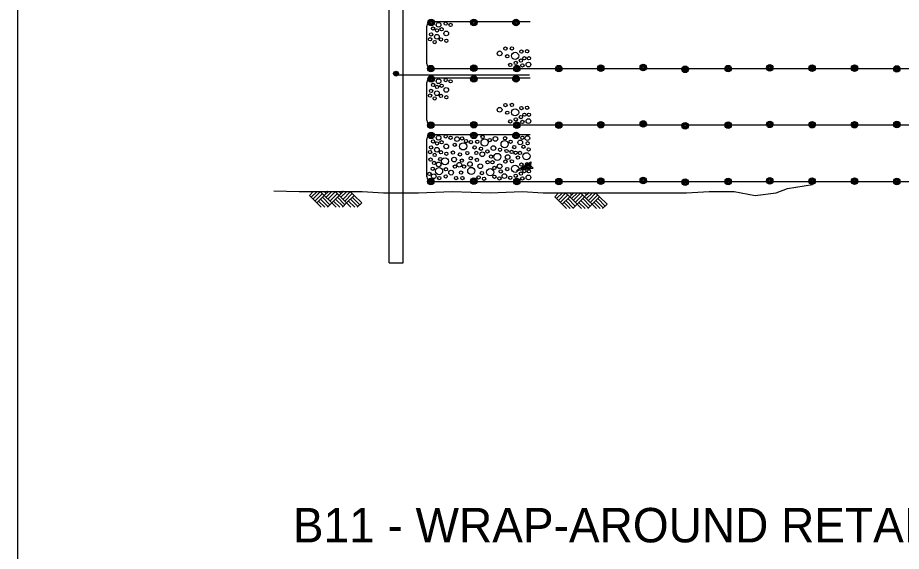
# Model space of a CAD drawing. Extents: x -0.04 to 2.79, y -0.02 to 1.81.
# Drawn here: x 2.1162 to 2.3837, y 0.9292 to 1.0907 of the extents above; entities that cross this region are included whole.
import ezdxf

# ---------------------------------------------------------------- set-up
doc = ezdxf.new("R2010")
doc.units = 0
doc.layers.add('Level 1', color=7, linetype='Continuous')

msp = doc.modelspace()

# ---------------------------------------------------------------- linework, layer by layer
msp.add_line((2.11617, 1.73185), (2.11617, 0.08028))
at = {"layer": 'Level 1'}
for p, q in [((2.22861, 1.03829), (2.22861, 1.23015)), ((2.23285, 1.03829), (2.23285, 1.23015)), ((2.2414, 1.08955), (2.27133, 1.08955)), ((2.24003, 1.07677), (2.24003, 1.08818)), ((2.23066, 1.07342), (2.27113, 1.07342)), ((2.24003, 1.07533), (2.24003, 1.07533)), ((2.2414, 1.07533), (2.39949, 1.07533)), ((2.24003, 1.05968), (2.24003, 1.07109)), ((2.2414, 1.07246), (2.27133, 1.07246)), ((2.24003, 1.05824), (2.24003, 1.05824)), ((2.2414, 1.05824), (2.4012, 1.05824)), ((2.2414, 1.05537), (2.27133, 1.05537)), ((2.24003, 1.04259), (2.24003, 1.05401)), ((2.26723, 1.04444), (2.27154, 1.0471)), ((2.26846, 1.04485), (2.2712, 1.04656)), ((2.26962, 1.04526), (2.27092, 1.04608)), ((2.27092, 1.04608), (2.27092, 1.04574)), ((2.2712, 1.04656), (2.27113, 1.0458)), ((2.27154, 1.0471), (2.2714, 1.04594)), ((2.26723, 1.04444), (2.27222, 1.04512)), ((2.26846, 1.04485), (2.27167, 1.04526)), ((2.26962, 1.04526), (2.27113, 1.04546)), ((2.27092, 1.04574), (2.27113, 1.04546)), ((2.27113, 1.0458), (2.27167, 1.04526)), ((2.2714, 1.04594), (2.27222, 1.04512)), ((2.24003, 1.04116), (2.24003, 1.04116)), ((2.2414, 1.04116), (2.40462, 1.04116)), ((2.20449, 1.03692), (2.20565, 1.03815)), ((2.20503, 1.03637), (2.20681, 1.03815)), ((2.20558, 1.03582), (2.20784, 1.03808)), ((2.209, 1.03692), (2.20777, 1.03815)), ((2.20954, 1.03753), (2.20893, 1.03815)), ((2.209, 1.03692), (2.21023, 1.03815)), ((2.209, 1.03692), (2.21023, 1.03815)), ((2.20954, 1.03637), (2.21132, 1.03815)), ((2.21009, 1.03808), (2.21002, 1.03815)), ((2.21009, 1.03582), (2.21241, 1.03808)), ((2.21351, 1.03692), (2.21228, 1.03815)), ((2.21405, 1.03753), (2.21344, 1.03815)), ((2.21351, 1.03692), (2.21474, 1.03815)), ((2.21351, 1.03692), (2.21474, 1.03815)), ((2.21405, 1.03637), (2.21583, 1.03815)), ((2.21467, 1.03808), (2.21453, 1.03815)), ((2.21467, 1.03582), (2.21693, 1.03808)), ((2.21802, 1.03692), (2.21686, 1.03815)), ((2.22861, 1.01648), (2.22861, 1.03829)), ((2.23285, 1.01648), (2.23285, 1.03829)), ((2.20674, 1.03466), (2.20449, 1.03692)), ((2.20613, 1.03521), (2.20845, 1.03753)), ((2.20674, 1.03466), (2.209, 1.03692)), ((2.21009, 1.03357), (2.20784, 1.03582)), ((2.21071, 1.03412), (2.20845, 1.03637)), ((2.21125, 1.03466), (2.209, 1.03692)), ((2.21071, 1.03521), (2.21296, 1.03753)), ((2.21125, 1.03466), (2.21351, 1.03692)), ((2.21467, 1.03357), (2.21241, 1.03582)), ((2.21522, 1.03412), (2.21296, 1.03637)), ((2.21706, 1.03336), (2.21351, 1.03692)), ((2.21522, 1.03521), (2.21747, 1.03753)), ((2.21576, 1.03466), (2.21802, 1.03692)), ((2.21918, 1.03357), (2.21693, 1.03582)), ((2.21973, 1.03412), (2.21747, 1.03637)), ((2.22034, 1.03466), (2.21802, 1.03692)), ((2.27878, 1.03651), (2.27995, 1.03774)), ((2.28104, 1.03425), (2.27878, 1.03651)), ((2.27933, 1.03596), (2.28111, 1.03774)), ((2.27988, 1.03535), (2.28213, 1.03767)), ((2.28042, 1.0348), (2.28275, 1.03706)), ((2.28104, 1.03425), (2.28329, 1.03651)), ((2.28329, 1.03651), (2.28206, 1.03774)), ((2.28439, 1.03309), (2.28213, 1.03535)), ((2.285, 1.03371), (2.28275, 1.03596)), ((2.28384, 1.03706), (2.28323, 1.03774)), ((2.28329, 1.03651), (2.28452, 1.03774)), ((2.28329, 1.03651), (2.28452, 1.03774)), ((2.28555, 1.03425), (2.28329, 1.03651)), ((2.28384, 1.03596), (2.28562, 1.03774)), ((2.28439, 1.03767), (2.28432, 1.03774)), ((2.28439, 1.03535), (2.28671, 1.03767)), ((2.285, 1.0348), (2.28726, 1.03706)), ((2.28555, 1.03425), (2.28781, 1.03651)), ((2.28781, 1.03651), (2.28658, 1.03774)), ((2.28897, 1.03309), (2.28671, 1.03535)), ((2.28951, 1.03371), (2.28726, 1.03596)), ((2.28835, 1.03706), (2.28774, 1.03774)), ((2.28781, 1.03651), (2.28904, 1.03774)), ((2.28781, 1.03651), (2.28904, 1.03774)), ((2.29136, 1.03295), (2.28781, 1.03651)), ((2.28835, 1.03596), (2.2902, 1.03774)), ((2.28897, 1.03767), (2.2889, 1.03774)), ((2.28897, 1.03535), (2.29122, 1.03767)), ((2.28951, 1.0348), (2.29177, 1.03706)), ((2.29006, 1.03425), (2.29232, 1.03651)), ((2.29232, 1.03651), (2.29115, 1.03774)), ((2.29348, 1.03309), (2.29122, 1.03535)), ((2.29403, 1.03371), (2.29177, 1.03596)), ((2.29464, 1.03425), (2.29232, 1.03651)), ((2.20804, 1.03336), (2.20674, 1.03466)), ((2.20913, 1.03336), (2.20729, 1.03521)), ((2.20995, 1.03336), (2.21125, 1.03466)), ((2.21255, 1.03336), (2.21125, 1.03466)), ((2.21371, 1.03336), (2.2118, 1.03521)), ((2.21447, 1.03336), (2.21576, 1.03466)), ((2.21822, 1.03336), (2.21638, 1.03521)), ((2.21898, 1.03336), (2.22034, 1.03466)), ((2.28234, 1.03295), (2.28104, 1.03425)), ((2.28343, 1.03295), (2.28159, 1.0348)), ((2.28425, 1.03295), (2.28555, 1.03425)), ((2.28685, 1.03295), (2.28555, 1.03425)), ((2.28801, 1.03295), (2.2861, 1.0348)), ((2.28876, 1.03295), (2.29006, 1.03425)), ((2.29252, 1.03295), (2.29068, 1.0348)), ((2.29327, 1.03295), (2.29464, 1.03425)), ((2.22861, 1.01648), (2.23285, 1.01648))]:
    msp.add_line(p, q, dxfattribs=at)
for points in [[(2.19375, 1.03829), (2.20141, 1.03815), (2.20524, 1.03815), (2.21071, 1.03815), (2.21453, 1.03815), (2.22048, 1.03815), (2.2269, 1.03774), (2.23066, 1.03774), (2.2375, 1.03774), (2.24768, 1.03815), (2.25917, 1.03774), (2.26894, 1.03815), (2.2753, 1.03774), (2.28466, 1.03774), (2.29225, 1.03774), (2.3012, 1.03774), (2.30886, 1.03774), (2.31863, 1.03774), (2.32547, 1.03815), (2.33305, 1.03815), (2.33948, 1.03685)], [(2.33948, 1.03685), (2.34584, 1.03774), (2.34925, 1.03897), (2.35684, 1.04027)]]:
    msp.add_lwpolyline(points, dxfattribs=at)
for centre, radius in [((2.24138, 1.08926), 0.000988), ((2.24138, 1.08926), 0.000766), ((2.24138, 1.08926), 0.000562), ((2.24138, 1.08926), 0.000284), ((2.24359, 1.08856), 0.000712), ((2.24575, 1.08893), 0.000498), ((2.24722, 1.08853), 0.000498), ((2.25427, 1.08926), 0.000988), ((2.25427, 1.08926), 0.000766), ((2.25427, 1.08926), 0.000562), ((2.25427, 1.08926), 0.000284), ((2.26704, 1.08926), 0.000988), ((2.26704, 1.08926), 0.000766), ((2.26704, 1.08926), 0.000562), ((2.26704, 1.08926), 0.000284), ((2.24133, 1.08564), 0.000498), ((2.24192, 1.08744), 0.000498), ((2.24312, 1.08684), 0.000498), ((2.24452, 1.0872), 0.000498), ((2.24592, 1.08594), 0.000712), ((2.24103, 1.08421), 0.000498), ((2.24242, 1.08334), 0.000498), ((2.24309, 1.08494), 0.000712), ((2.24432, 1.08414), 0.000498), ((2.24595, 1.08371), 0.000498), ((2.26382, 1.08135), 0.000498), ((2.26581, 1.08141), 0.000498), ((2.26867, 1.08045), 0.000498), ((2.2704, 1.08055), 0.000498), ((2.26209, 1.07992), 0.000712), ((2.26438, 1.07905), 0.000498), ((2.26678, 1.07915), 0.00108), ((2.26851, 1.07772), 0.000498), ((2.2696, 1.07845), 0.000498), ((2.27097, 1.07842), 0.000498), ((2.24128, 1.0753), 0.000988), ((2.24128, 1.0753), 0.000766), ((2.24128, 1.0753), 0.000562), ((2.24128, 1.0753), 0.000284), ((2.25427, 1.07541), 0.000988), ((2.25427, 1.07541), 0.000766), ((2.25427, 1.07541), 0.000562), ((2.25427, 1.07541), 0.000284), ((2.26531, 1.07642), 0.000498), ((2.26726, 1.0753), 0.000988), ((2.26698, 1.07702), 0.000498), ((2.26726, 1.0753), 0.000766), ((2.26726, 1.0753), 0.000562), ((2.26726, 1.0753), 0.000284), ((2.26897, 1.07626), 0.000498), ((2.2708, 1.07652), 0.000712), ((2.28003, 1.0753), 0.000988), ((2.28003, 1.0753), 0.000766), ((2.28003, 1.0753), 0.000562), ((2.28003, 1.0753), 0.000284), ((2.29269, 1.07541), 0.000988), ((2.29269, 1.07541), 0.000766), ((2.29269, 1.07541), 0.000562), ((2.29269, 1.07541), 0.000284), ((2.30557, 1.07562), 0.000988), ((2.30557, 1.07562), 0.000766), ((2.30557, 1.07562), 0.000562), ((2.30557, 1.07562), 0.000284), ((2.31824, 1.07508), 0.000988), ((2.31824, 1.07508), 0.000766), ((2.31824, 1.07508), 0.000562), ((2.33127, 1.0753), 0.000988), ((2.33127, 1.0753), 0.000766), ((2.33127, 1.0753), 0.000562), ((2.33127, 1.0753), 0.000284), ((2.34385, 1.07551), 0.000988), ((2.34385, 1.07551), 0.000766), ((2.34385, 1.07551), 0.000562), ((2.34385, 1.07551), 0.000284), ((2.35667, 1.07541), 0.000988), ((2.35667, 1.07541), 0.000766), ((2.35667, 1.07541), 0.000562), ((2.35667, 1.07541), 0.000284), ((2.36955, 1.07541), 0.000988), ((2.36955, 1.07541), 0.000766), ((2.36955, 1.07541), 0.000562), ((2.36955, 1.07541), 0.000284), ((2.38233, 1.0752), 0.000988), ((2.38233, 1.0752), 0.000766), ((2.38233, 1.0752), 0.000562), ((2.38233, 1.0752), 0.000284), ((2.23071, 1.07379), 0.000741), ((2.23071, 1.07379), 0.000575), ((2.23071, 1.07379), 0.000421), ((2.23071, 1.07379), 0.000213), ((2.24138, 1.07217), 0.000988), ((2.24138, 1.07217), 0.000766), ((2.25427, 1.07217), 0.000988), ((2.25427, 1.07217), 0.000766), ((2.26704, 1.07217), 0.000988), ((2.26704, 1.07217), 0.000766), ((2.31824, 1.07508), 0.000284), ((2.24138, 1.07217), 0.000562), ((2.24138, 1.07217), 0.000284), ((2.24192, 1.07035), 0.000498), ((2.24312, 1.06975), 0.000498), ((2.24359, 1.07148), 0.000712), ((2.24452, 1.07011), 0.000498), ((2.24575, 1.07184), 0.000498), ((2.24722, 1.07145), 0.000498), ((2.25427, 1.07217), 0.000562), ((2.25427, 1.07217), 0.000284), ((2.26704, 1.07217), 0.000562), ((2.26704, 1.07217), 0.000284), ((2.24103, 1.06712), 0.000498), ((2.24133, 1.06855), 0.000498), ((2.24309, 1.06785), 0.000712), ((2.24432, 1.06705), 0.000498), ((2.24592, 1.06885), 0.000712), ((2.24242, 1.06626), 0.000498), ((2.24595, 1.06662), 0.000498), ((2.26382, 1.06426), 0.000498), ((2.26581, 1.06433), 0.000498), ((2.26209, 1.06283), 0.000712), ((2.26438, 1.06196), 0.000498), ((2.26678, 1.06206), 0.00108), ((2.26867, 1.06336), 0.000498), ((2.2704, 1.06346), 0.000498), ((2.26531, 1.05933), 0.000498), ((2.26698, 1.05993), 0.000498), ((2.26851, 1.06063), 0.000498), ((2.26897, 1.05917), 0.000498), ((2.2696, 1.06136), 0.000498), ((2.2708, 1.05943), 0.000712), ((2.27097, 1.06133), 0.000498), ((2.30557, 1.05854), 0.000988), ((2.34385, 1.05842), 0.000988), ((2.24128, 1.05821), 0.000988), ((2.24128, 1.05821), 0.000766), ((2.24128, 1.05821), 0.000562), ((2.24128, 1.05821), 0.000284), ((2.25427, 1.05832), 0.000988), ((2.25427, 1.05832), 0.000766), ((2.25427, 1.05832), 0.000562), ((2.25427, 1.05832), 0.000284), ((2.26726, 1.05821), 0.000988), ((2.26726, 1.05821), 0.000766), ((2.26726, 1.05821), 0.000562), ((2.26726, 1.05821), 0.000284), ((2.28003, 1.05821), 0.000988), ((2.28003, 1.05821), 0.000766), ((2.28003, 1.05821), 0.000562), ((2.28003, 1.05821), 0.000284), ((2.29269, 1.05832), 0.000988), ((2.29269, 1.05832), 0.000766), ((2.29269, 1.05832), 0.000562), ((2.29269, 1.05832), 0.000284), ((2.30557, 1.05854), 0.000766), ((2.30557, 1.05854), 0.000562), ((2.30557, 1.05854), 0.000284), ((2.31824, 1.05799), 0.000988), ((2.31824, 1.05799), 0.000766), ((2.31824, 1.05799), 0.000562), ((2.31824, 1.05799), 0.000284), ((2.33127, 1.05821), 0.000988), ((2.33127, 1.05821), 0.000766), ((2.33127, 1.05821), 0.000562), ((2.33127, 1.05821), 0.000284), ((2.34385, 1.05842), 0.000766), ((2.34385, 1.05842), 0.000562), ((2.34385, 1.05842), 0.000284), ((2.35667, 1.05832), 0.000988), ((2.35667, 1.05832), 0.000766), ((2.35667, 1.05832), 0.000562), ((2.35667, 1.05832), 0.000284), ((2.36955, 1.05832), 0.000988), ((2.36955, 1.05832), 0.000766), ((2.36955, 1.05832), 0.000562), ((2.36955, 1.05832), 0.000284), ((2.38233, 1.05836), 0.000988), ((2.38233, 1.05836), 0.000766), ((2.38233, 1.05836), 0.000562), ((2.38233, 1.05836), 0.000284), ((2.24138, 1.05509), 0.000988), ((2.24138, 1.05509), 0.000766), ((2.24138, 1.05509), 0.000562), ((2.24138, 1.05509), 0.000284), ((2.24359, 1.05439), 0.000712), ((2.24575, 1.05476), 0.000498), ((2.24722, 1.05436), 0.000498), ((2.24918, 1.05399), 0.000712), ((2.25071, 1.05416), 0.000498), ((2.25427, 1.05509), 0.000988), ((2.25427, 1.05509), 0.000766), ((2.25427, 1.05509), 0.000562), ((2.25427, 1.05509), 0.000284), ((2.2569, 1.05462), 0.000498), ((2.25909, 1.05366), 0.000498), ((2.26079, 1.05402), 0.000712), ((2.26372, 1.05422), 0.000498), ((2.26704, 1.05509), 0.000988), ((2.26704, 1.05509), 0.000766), ((2.26704, 1.05509), 0.000562), ((2.26704, 1.05509), 0.000284), ((2.26897, 1.05436), 0.000498), ((2.27047, 1.05426), 0.000712), ((2.24133, 1.05146), 0.000498), ((2.24192, 1.05326), 0.000498), ((2.24309, 1.05076), 0.000712), ((2.24312, 1.05266), 0.000498), ((2.24452, 1.05303), 0.000498), ((2.24592, 1.05176), 0.000712), ((2.24851, 1.05223), 0.000498), ((2.25104, 1.05176), 0.00108), ((2.25191, 1.05336), 0.000498), ((2.2534, 1.05306), 0.000498), ((2.2545, 1.05146), 0.000498), ((2.2553, 1.05316), 0.000498), ((2.2564, 1.05106), 0.000498), ((2.25753, 1.05293), 0.00108), ((2.26019, 1.05123), 0.000712), ((2.26358, 1.05243), 0.00108), ((2.26541, 1.05316), 0.000498), ((2.26651, 1.05156), 0.000498), ((2.26831, 1.05296), 0.000712), ((2.26931, 1.05166), 0.000498), ((2.27057, 1.05273), 0.000498), ((2.27087, 1.05086), 0.000498), ((2.24103, 1.05003), 0.000498), ((2.24242, 1.04917), 0.000498), ((2.24432, 1.04997), 0.000498), ((2.24595, 1.04953), 0.000498), ((2.24795, 1.04987), 0.000498), ((2.25004, 1.04933), 0.000498), ((2.2523, 1.04973), 0.000498), ((2.25503, 1.04977), 0.000498), ((2.25683, 1.04937), 0.000712), ((2.25839, 1.05023), 0.000498), ((2.25949, 1.04867), 0.000498), ((2.26139, 1.04857), 0.00108), ((2.26219, 1.05076), 0.000498), ((2.26418, 1.05037), 0.000498), ((2.26451, 1.04854), 0.000712), ((2.26568, 1.05007), 0.000498), ((2.26691, 1.04983), 0.000498), ((2.26761, 1.04837), 0.000498), ((2.26821, 1.04977), 0.000498), ((2.2702, 1.04877), 0.00108), ((2.24116, 1.04777), 0.000498), ((2.24226, 1.04674), 0.000498), ((2.24362, 1.04631), 0.000712), ((2.24412, 1.04794), 0.000498), ((2.24555, 1.04724), 0.00108), ((2.24831, 1.04777), 0.000712), ((2.24855, 1.04564), 0.000498), ((2.24988, 1.04621), 0.000712), ((2.25064, 1.04747), 0.000498), ((2.25131, 1.04567), 0.000498), ((2.2531, 1.04641), 0.000712), ((2.25334, 1.04817), 0.000498), ((2.2552, 1.04767), 0.000498), ((2.25623, 1.04577), 0.000712), ((2.25843, 1.04694), 0.000498), ((2.25989, 1.04697), 0.000498), ((2.26209, 1.04574), 0.000712), ((2.26382, 1.04717), 0.000498), ((2.26581, 1.04724), 0.000498), ((2.26678, 1.04498), 0.00108), ((2.26867, 1.04627), 0.000498), ((2.2704, 1.04637), 0.000498), ((2.24083, 1.04344), 0.000498), ((2.24183, 1.04498), 0.000498), ((2.24213, 1.04271), 0.000712), ((2.24375, 1.04428), 0.00108), ((2.24582, 1.04484), 0.000498), ((2.24741, 1.04381), 0.000712), ((2.25041, 1.04384), 0.000498), ((2.2535, 1.04434), 0.00108), ((2.2567, 1.04368), 0.000498), ((2.25922, 1.04394), 0.00108), ((2.26049, 1.04524), 0.000498), ((2.26242, 1.04418), 0.000498), ((2.26352, 1.04275), 0.000712), ((2.26438, 1.04488), 0.000498), ((2.26698, 1.04285), 0.000498), ((2.26851, 1.04354), 0.000498), ((2.2696, 1.04428), 0.000498), ((2.27097, 1.04424), 0.000498), ((2.24128, 1.04112), 0.000988), ((2.24128, 1.04112), 0.000766), ((2.24128, 1.04112), 0.000562), ((2.24128, 1.04112), 0.000284), ((2.24382, 1.04215), 0.000498), ((2.24575, 1.04265), 0.000498), ((2.24891, 1.04215), 0.000498), ((2.25084, 1.04218), 0.000498), ((2.25427, 1.04123), 0.000988), ((2.25427, 1.04123), 0.000766), ((2.25427, 1.04123), 0.000562), ((2.25427, 1.04123), 0.000284), ((2.25573, 1.04238), 0.000498), ((2.2574, 1.04195), 0.000498), ((2.26049, 1.04258), 0.000498), ((2.26202, 1.04208), 0.000498), ((2.26531, 1.04225), 0.000498), ((2.26726, 1.04112), 0.000988), ((2.26726, 1.04112), 0.000766), ((2.26726, 1.04112), 0.000562), ((2.26726, 1.04112), 0.000284), ((2.26897, 1.04208), 0.000498), ((2.2708, 1.04235), 0.000712), ((2.28003, 1.04112), 0.000988), ((2.28003, 1.04112), 0.000766), ((2.28003, 1.04112), 0.000562), ((2.28003, 1.04112), 0.000284), ((2.29269, 1.04123), 0.000988), ((2.29269, 1.04123), 0.000766), ((2.29269, 1.04123), 0.000562), ((2.29269, 1.04123), 0.000284), ((2.30557, 1.04145), 0.000988), ((2.30557, 1.04145), 0.000766), ((2.30557, 1.04145), 0.000562), ((2.30557, 1.04145), 0.000284), ((2.31824, 1.04091), 0.000988), ((2.31824, 1.04091), 0.000766), ((2.31824, 1.04091), 0.000562), ((2.31824, 1.04091), 0.000284), ((2.33127, 1.04112), 0.000988), ((2.33127, 1.04112), 0.000766), ((2.33127, 1.04112), 0.000562), ((2.33127, 1.04112), 0.000284), ((2.34385, 1.04133), 0.000988), ((2.34385, 1.04133), 0.000766), ((2.34385, 1.04133), 0.000562), ((2.34385, 1.04133), 0.000284), ((2.35667, 1.04123), 0.000988), ((2.35667, 1.04123), 0.000766), ((2.35667, 1.04123), 0.000562), ((2.35667, 1.04123), 0.000284), ((2.36955, 1.04123), 0.000988), ((2.36955, 1.04123), 0.000766), ((2.36955, 1.04123), 0.000562), ((2.36955, 1.04123), 0.000284), ((2.38233, 1.04115), 0.000988), ((2.38233, 1.04115), 0.000766), ((2.38233, 1.04115), 0.000562), ((2.38233, 1.04115), 0.000284)]:
    msp.add_circle(centre, radius, dxfattribs=at)
for centre, start, end in [((2.24144, 1.08817), 90, 180), ((2.24144, 1.07678), 180, 270), ((2.24144, 1.07108), 90, 180), ((2.24144, 1.05969), 180, 270), ((2.24144, 1.05399), 90, 180), ((2.24144, 1.0426), 180, 270)]:
    msp.add_arc(centre, 0.00142, start, end, dxfattribs=at)

# ---------------------------------------------------------------- texts
msp.add_text('B11 - WRAP-AROUND RETAINING WALL', height=0.0104167).set_placement((2.19947, 0.93191))

doc.saveas('drawing.dxf')
